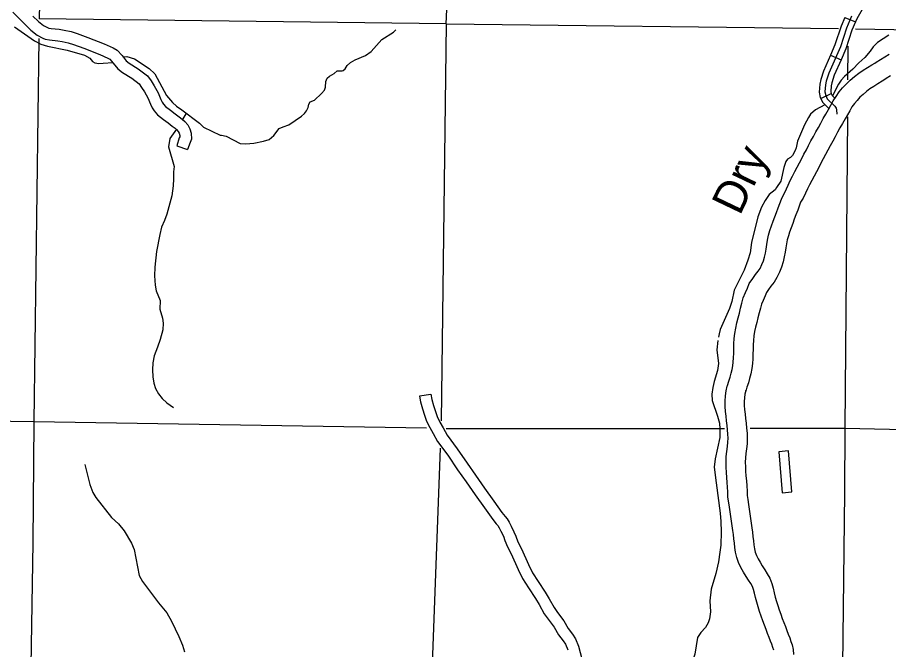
# Model space of a CAD drawing. Extents: x 0 to 3171, y 0 to 2059.
# Drawn here: x 1493 to 1682.3, y 804.5 to 941.8 of the extents above; entities that cross this region are included whole.
import ezdxf

# ---------------------------------------------------------------- set-up
doc = ezdxf.new("R2010")
doc.units = 0
for name, color, linetype in [('Level 10', 7, 'Continuous'), ('Level 32', 7, 'Continuous'), ('Level 35', 7, 'Continuous'), ('Level 46', 7, 'Continuous'), ('Level 5', 7, 'Continuous'), ('Level 57', 7, 'Continuous')]:
    doc.layers.add(name, color=color, linetype=linetype)

msp = doc.modelspace()

# ---------------------------------------------------------------- linework, layer by layer
at = {"layer": 'Level 10'}
for p, q in [((1647.22, 861.7), (1647.25, 861.83)), ((1651.23, 860.6), (1651.27, 860.73))]:
    msp.add_line(p, q, dxfattribs=at)
for points in [[(1647.25, 861.83), (1647.54, 862.76), (1647.83, 863.63), (1648.08, 864.48), (1648.32, 865.31), (1648.46, 866.06), (1648.54, 866.88), (1648.58, 867.81), (1648.63, 868.81), (1648.66, 869.8), (1648.68, 870.86), (1648.76, 872), (1648.88, 873.13), (1649.07, 874.29), (1649.32, 875.42), (1649.59, 876.5), (1649.85, 877.56), (1650.12, 878.63), (1650.4, 879.7), (1650.71, 880.86), (1651.21, 882.04), (1651.64, 882.92), (1652.01, 883.94), (1652.77, 885.04), (1653.39, 885.89), (1653.97, 886.62), (1654.34, 887.23), (1654.76, 888.12), (1655.08, 888.91), (1655.32, 889.71), (1655.51, 890.55), (1655.67, 891.45), (1655.83, 892.41), (1656, 893.41), (1656.22, 894.45), (1656.51, 895.49), (1656.84, 896.51), (1657.19, 897.48), (1657.53, 898.43), (1657.9, 899.42), (1658.28, 900.4), (1658.65, 901.34), (1658.98, 902.28), (1660.09, 904.54), (1660.49, 905.36), (1660.92, 906.31), (1661.42, 907.31), (1661.92, 908.27), (1662.41, 909.22), (1662.9, 910.17), (1663.4, 911.12), (1663.9, 912.08), (1664.41, 913.01), (1664.88, 913.94), (1665.42, 914.94), (1665.96, 915.91), (1666.49, 916.88), (1667.02, 917.85), (1667.54, 918.82), (1668.09, 919.81), (1668.65, 920.78), (1669.2, 921.76), (1669.71, 922.68), (1670.25, 923.64), (1670.87, 924.62), (1671.54, 925.57), (1672.29, 926.49), (1673.1, 927.35), (1673.96, 928.16), (1674.86, 928.92), (1675.82, 929.64), (1676.79, 930.28), (1677.73, 930.86), (1678.66, 931.44), (1679.3, 931.84), (1679.59, 932.02), (1680.53, 932.6), (1681.47, 933.18), (1682.41, 933.76)], [(1682.72, 929.06), (1681.79, 928.48), (1681.5, 928.3), (1680.86, 927.9), (1679.94, 927.33), (1679.04, 926.77), (1678.21, 926.22), (1677.45, 925.66), (1676.73, 925.05), (1676.05, 924.41), (1675.43, 923.75), (1674.86, 923.05), (1674.33, 922.31), (1673.84, 921.51), (1673.34, 920.64), (1672.83, 919.73), (1672.27, 918.72), (1671.72, 917.76), (1671.2, 916.82), (1670.68, 915.86), (1670.14, 914.88), (1669.61, 913.9), (1669.07, 912.94), (1668.58, 912.02), (1668.09, 911.06), (1667.57, 910.11), (1667.09, 909.18), (1666.6, 908.25), (1666.11, 907.31), (1665.62, 906.35), (1665.13, 905.42), (1664.68, 904.52), (1664.26, 903.58), (1663.73, 902.51), (1663.17, 901.62), (1662.55, 899.88), (1662.16, 898.89), (1661.79, 897.94), (1661.45, 897), (1661.11, 896.06), (1660.78, 895.15), (1660.5, 894.3), (1660.27, 893.47), (1660.09, 892.62), (1659.94, 891.72), (1659.78, 890.76), (1659.6, 889.73), (1659.36, 888.64), (1659.02, 887.52), (1658.57, 886.43), (1658.01, 885.25), (1657.4, 884.25), (1656.72, 883.38), (1656.17, 882.63), (1655.74, 882.01), (1655.48, 881.3), (1655, 880.31), (1654.66, 879.5), (1654.43, 878.64), (1654.16, 877.6), (1653.9, 876.54), (1653.63, 875.49), (1653.38, 874.47), (1653.17, 873.51), (1653.01, 872.57), (1652.91, 871.62), (1652.84, 870.68), (1652.83, 869.69), (1652.79, 868.64), (1652.75, 867.63), (1652.7, 866.59), (1652.59, 865.47), (1652.38, 864.34), (1652.08, 863.33), (1651.81, 862.39), (1651.51, 861.48), (1651.23, 860.6)], [(1657.34, 804.29), (1657.12, 804.9), (1656.9, 805.59), (1656.62, 806.29), (1656.3, 807.11), (1655.97, 807.96), (1655.65, 808.82), (1655.29, 809.74), (1654.94, 810.72), (1654.59, 811.69), (1654.24, 812.7), (1653.92, 813.74), (1653.63, 814.77), (1653.39, 815.79), (1653.18, 816.7), (1652.94, 817.5), (1652.69, 818.16), (1652.32, 818.81), (1651.87, 819.56), (1651.34, 820.35), (1650.76, 821.27), (1650.19, 822.27), (1649.7, 823.35), (1649.31, 824.46), (1649.05, 825.58), (1648.9, 826.6), (1648.78, 827.56), (1648.67, 828.49), (1648.55, 829.42), (1648.43, 830.35), (1648.29, 831.32), (1648.14, 832.32), (1648, 833.34), (1647.86, 834.37), (1647.72, 835.38), (1647.56, 836.36), (1647.36, 837.59), (1647.38, 838.75), (1647.31, 839.71), (1647.22, 840.76), (1647.13, 841.82), (1647.05, 842.92), (1646.99, 844.05), (1646.98, 845.2), (1647.02, 846.37), (1647.13, 847.51), (1647.26, 848.56), (1647.36, 849.47), (1647.39, 850.34), (1647.37, 851.22), (1647.28, 852.15), (1647.18, 853.15), (1647.06, 854.16), (1646.96, 855.17), (1646.85, 856.2), (1646.77, 857.27), (1646.74, 858.4), (1646.81, 859.55), (1646.97, 860.69), (1647.22, 861.7)], [(1651.27, 860.73), (1651.07, 859.9), (1650.96, 859.13), (1650.91, 858.33), (1650.93, 857.49), (1651, 856.57), (1651.1, 855.6), (1651.21, 854.61), (1651.32, 853.6), (1651.43, 852.57), (1651.53, 851.48), (1651.56, 850.33), (1651.52, 849.17), (1651.4, 848.06), (1651.27, 847.05), (1651.18, 846.1), (1651.15, 845.15), (1651.16, 844.18), (1651.2, 843.19), (1651.29, 842.16), (1651.38, 841.1), (1651.46, 840.03), (1651.55, 838.87), (1651.53, 837.9), (1651.67, 837.05), (1651.85, 835.98), (1651.99, 834.93), (1652.13, 833.92), (1652.27, 832.91), (1652.41, 831.91), (1652.55, 830.93), (1652.68, 829.96), (1652.81, 829.01), (1652.92, 828.07), (1653.03, 827.17), (1653.15, 826.35), (1653.32, 825.62), (1653.57, 824.9), (1653.91, 824.17), (1654.34, 823.41), (1654.84, 822.62), (1655.39, 821.78), (1655.92, 820.91), (1656.47, 819.93), (1656.89, 818.84), (1657.21, 817.77), (1657.44, 816.75), (1657.67, 815.81), (1657.92, 814.91), (1658.19, 814.01), (1658.52, 813.08), (1658.86, 812.12), (1659.19, 811.2), (1659.54, 810.31), (1659.87, 809.43), (1660.19, 808.61), (1660.49, 807.83), (1660.82, 807.02), (1661.07, 806.23), (1661.34, 805.47), (1661.58, 804.5), (1661.6, 803.4)]]:
    msp.add_lwpolyline(points, dxfattribs=at)
at = {"layer": 'Level 32'}
for p, q in [((1672.77, 941.76), (1675.07, 940.79)), ((1669.65, 933.56), (1671.95, 932.56)), ((1667.54, 924.17), (1669.79, 925.25))]:
    msp.add_line(p, q, dxfattribs=at)
for points in [[(1679.83, 947.9), (1678.95, 946.55), (1676.56, 943.45), (1675.35, 941.44), (1675.07, 940.79)], [(1674.23, 942.01), (1673.13, 939.41), (1671.8, 935.36), (1669.31, 929.63), (1668.75, 927.91), (1668.56, 927.11), (1668.46, 925.62), (1668.63, 924.77), (1668.96, 924.09), (1670.6, 922.52), (1670.87, 922.07), (1670.97, 921.72), (1671.02, 920.74)], [(1672.77, 941.76), (1671.96, 939.85), (1670.63, 935.8), (1669.65, 933.56)], [(1675.07, 940.79), (1674.3, 938.97), (1672.97, 934.91), (1671.95, 932.56)], [(1669.65, 933.56), (1668.14, 930.08), (1667.54, 928.25), (1667.31, 927.29), (1667.2, 925.53), (1667.44, 924.37), (1667.54, 924.17)], [(1671.95, 932.56), (1670.48, 929.19), (1669.95, 927.57), (1669.8, 926.92), (1669.72, 925.71), (1669.83, 925.18), (1669.79, 925.25)], [(1667.54, 924.17), (1667.93, 923.34), (1669.33, 922)], [(1669.79, 925.25), (1669.99, 924.84), (1670.62, 924.23)]]:
    msp.add_lwpolyline(points, dxfattribs=at)
at = {"layer": 'Level 35'}
for points in [[(1492.36, 939.7), (1496.67, 936.65), (1498.08, 935.99), (1499.48, 935.54), (1503.77, 934.63), (1507.54, 933.56), (1508.71, 932.95), (1509.28, 932.19), (1509.83, 931.89), (1510.7, 931.78), (1511.63, 931.86), (1513.73, 931.94)], [(1537.06, 916.18), (1537.35, 916.19), (1538.34, 916), (1541.37, 914.36), (1542.6, 914.31), (1544.32, 914.42), (1546.46, 914.87), (1547.69, 915.26), (1548.69, 916.09), (1549.85, 917.61), (1550.69, 918.03), (1551.99, 918.4), (1554.74, 920.29), (1555.35, 920.89), (1555.77, 921.46), (1556.14, 922.18), (1556.31, 922.94), (1556.57, 923.46), (1557.53, 923.78), (1559.06, 925.22), (1559.72, 925.96), (1559.94, 926.63), (1560.02, 927.85), (1560.31, 928.58), (1560.78, 929.02), (1561.81, 929.62), (1562.45, 930.19), (1563.52, 930.19), (1563.75, 930.26), (1564.23, 930.62), (1564.66, 931.35), (1565.35, 931.96), (1566.36, 932.54), (1568.58, 933.49), (1569.87, 934.33), (1572.16, 936.94), (1574.72, 938.55), (1575.19, 939.08)], [(1682.35, 937.88), (1679.9, 936.33), (1678.93, 935.39), (1678.3, 934.45), (1677.09, 933.04), (1675.79, 931.9), (1674.52, 930.54), (1672.69, 928.94), (1672.01, 928.12), (1671.41, 927.29), (1670.11, 924.72)], [(1515.91, 933.21), (1516.75, 933.3), (1518.45, 932.79), (1521.6, 930.64), (1522.81, 929.49), (1525.37, 924.77), (1526.68, 923.27), (1527.56, 922.5), (1528.74, 921.7), (1532.53, 918.78), (1533.4, 917.95), (1537.06, 916.18)], [(1668.42, 922.79), (1666.37, 921.7), (1665.29, 920.75), (1664.85, 920.05), (1664.02, 918.46), (1662.49, 914.87), (1662.22, 913.42), (1661.99, 912.86), (1661.43, 911.76), (1660.99, 911.33), (1660.29, 910.95), (1659.93, 910.46), (1659.52, 909.15), (1658.84, 906.23), (1657.92, 904.79), (1657.63, 904.31), (1656.34, 903.29), (1655.43, 901.99), (1654.66, 900.52), (1653.84, 898.42), (1652.52, 892.88), (1652.19, 890.65), (1651.66, 889.01), (1650.88, 886.86), (1648.75, 882.49), (1648.23, 880.05), (1647.73, 878.56), (1645.68, 874.01), (1645.43, 873.04), (1645.34, 872.3)], [(1529.67, 920.98), (1528.84, 919.62)], [(1527.51, 917.47), (1526.13, 915.45), (1525.84, 913.62), (1527.05, 909.38), (1526.88, 908.23), (1526.92, 906.71), (1526.8, 905.16), (1526.51, 903), (1525.41, 899.04), (1524.95, 897.62), (1524.27, 896.17), (1523.9, 894.61), (1523.17, 890.91), (1522.84, 887.53), (1522.77, 885.66), (1522.9, 883.59), (1523.1, 882.41), (1523.99, 880.31), (1523.9, 878.37), (1524.53, 876.46), (1524.65, 875.36), (1524.57, 873.92), (1523.99, 871.81), (1523.39, 870.13)], [(1645.16, 871.58), (1644.97, 869.54), (1645.3, 866.61), (1645.11, 865.06), (1644.37, 862.7), (1644.09, 861.4), (1643.9, 859.91), (1643.94, 858.55), (1645.1, 855.16), (1645.51, 853.66), (1645.64, 852.41), (1645.58, 850.5), (1644.62, 845.9), (1644.37, 844.05), (1644.8, 840.67), (1645.71, 834.11), (1645.86, 832.25), (1645.92, 830.03), (1645.84, 827.16), (1645.59, 825.58), (1645.35, 823.54)], [(1523.39, 870.13), (1522.66, 868.23), (1522.39, 866.75), (1522.3, 865.21), (1522.43, 863.68), (1522.65, 862.31), (1523.01, 861.18), (1523.63, 859.97), (1524.45, 858.98), (1525.42, 858.07), (1526.86, 857.06)], [(1507.61, 844.65), (1508.69, 840.31), (1509.38, 838.55), (1510.05, 837.47), (1513.42, 833.11), (1514.94, 831.75), (1516.15, 830.21), (1517.74, 827.54), (1518.33, 826.22), (1519.4, 820.53), (1520.17, 819.27), (1523.64, 814.63), (1525.43, 812.42), (1526.44, 810.6), (1528.04, 807.31), (1528.84, 805.38), (1529.28, 803.93)], [(1645.35, 823.54), (1644.72, 820.99), (1643.75, 817.59), (1643.46, 815.03), (1643.55, 812.67), (1643.35, 811.1), (1643.09, 810.23), (1642.49, 809.26), (1641.47, 808.16), (1640.78, 807.11), (1640.21, 803.42), (1639.58, 801.74), (1638.55, 800.25), (1637.38, 798.82), (1636.78, 797.75), (1636.63, 796.78), (1636.51, 793.55), (1635.17, 789.82), (1635.03, 788.85)]]:
    msp.add_lwpolyline(points, dxfattribs=at)
at = {"layer": 'Level 46'}
for points in [[(1491.97, 942.93), (1494.57, 940.29), (1495.91, 939.02), (1497.26, 937.89), (1498.5, 937.29), (1499.03, 937.06), (1499.93, 936.87), (1501.76, 936.7), (1502.71, 936.56), (1503.98, 936.27), (1505.14, 935.9), (1507.39, 935.08), (1510.9, 933.69), (1512.65, 932.92), (1513.03, 932.69), (1513.81, 931.83), (1514.83, 930.57), (1515.79, 929.78), (1517.81, 928.57), (1519.4, 927.31), (1519.96, 926.55), (1520.57, 925.6), (1521.32, 924.3), (1521.88, 922.92), (1522.29, 922.12), (1522.72, 921.45), (1523.45, 920.6), (1524.74, 919.61), (1525.73, 918.85), (1526.6, 918.16), (1527.23, 917.7), (1527.58, 917.41), (1527.91, 917.02), (1528.12, 916.62), (1528.28, 916.14), (1528.3, 915.85), (1528.16, 915.58), (1527.59, 913.84), (1529.97, 913.06)], [(1496.32, 942.07), (1497.57, 940.89), (1498.63, 940.01), (1499.54, 939.57), (1499.8, 939.45), (1500.31, 939.35), (1502.06, 939.18), (1503.17, 939.02), (1504.65, 938.68), (1505.94, 938.26), (1508.28, 937.41), (1511.86, 936), (1513.8, 935.15), (1514.64, 934.64), (1515.71, 933.46), (1516.62, 932.34), (1517.24, 931.83), (1519.23, 930.63), (1521.21, 929.07), (1522.03, 927.96), (1522.71, 926.89), (1523.57, 925.4), (1524.15, 923.96), (1524.46, 923.36), (1524.73, 922.95), (1525.17, 922.43), (1526.26, 921.59), (1527.27, 920.82), (1528.11, 920.15), (1528.78, 919.67), (1529.35, 919.18), (1529.99, 918.44), (1530.43, 917.6), (1530.75, 916.62), (1530.83, 915.33), (1530.48, 914.62), (1529.97, 913.06)], [(1582.84, 859.89), (1580.37, 859.48), (1580.6, 858.26), (1580.97, 856.77), (1581.43, 855.34), (1581.9, 854.07), (1582.56, 852.7), (1583.29, 851.38), (1584.29, 849.68), (1586.47, 846.66), (1588.63, 843.49), (1590.48, 840.88), (1592.46, 838.05), (1594.44, 835.27), (1596.27, 832.72), (1597.04, 831.77), (1597.34, 831.4), (1597.63, 830.93), (1598.05, 830.14), (1598.59, 829.06), (1598.92, 828.18), (1599.48, 826.79), (1600.28, 825.27), (1601.77, 821.86), (1602.72, 819.89), (1604.04, 817.83), (1605.57, 815.57), (1606.33, 814.25), (1607.47, 812.2), (1608.33, 811.04)], [(1582.83, 859.94), (1583.04, 858.79), (1583.37, 857.46), (1583.79, 856.16), (1584.2, 855.05), (1584.78, 853.85), (1585.46, 852.62), (1586.39, 851.06), (1588.52, 848.09), (1590.68, 844.91), (1592.53, 842.32), (1594.5, 839.49), (1596.48, 836.72), (1598.26, 834.24), (1598.99, 833.34), (1599.39, 832.84), (1599.81, 832.16), (1600.27, 831.28), (1600.88, 830.06), (1601.25, 829.09), (1601.75, 827.84), (1602.53, 826.36), (1604.04, 822.9), (1604.9, 821.12), (1606.13, 819.21), (1607.69, 816.89), (1608.51, 815.48), (1609.58, 813.56), (1610.34, 812.52)], [(1610.33, 812.53), (1611.68, 810.67), (1612.64, 809.06), (1613.63, 807.77), (1614.26, 806.77), (1614.93, 805.17), (1615.62, 802.45)], [(1608.31, 811.06), (1609.58, 809.29), (1610.56, 807.66), (1611.57, 806.33), (1612.04, 805.6), (1612.55, 804.37)]]:
    msp.add_lwpolyline(points, dxfattribs=at)
at = {"layer": 'Level 5'}
for points in [[(1498.56, 980.12), (1497.71, 941.45)], [(1586.14, 940.38), (1586.39, 945.07), (1586.87, 979.5)], [(1586.14, 940.38), (1497.71, 941.45)], [(1586.14, 940.38), (1585.04, 854.15)], [(1586.14, 940.38), (1671.39, 939.37)], [(1675.08, 939.32), (1687.61, 939.08)], [(1497.65, 937.2), (1496.54, 853.94)], [(1673.44, 935.51), (1673.38, 928.22)], [(1673.32, 920.19), (1672.77, 852.52)], [(1496.54, 853.94), (1436.67, 854.81)], [(1496.54, 853.94), (1496.32, 827.64), (1495.33, 765.28)], [(1581.86, 852.52), (1496.54, 853.94)], [(1586.14, 852.47), (1646.59, 852.5)], [(1652.19, 852.51), (1672.77, 852.52)], [(1672.77, 852.52), (1672.72, 838.55), (1671.92, 769.6)], [(1672.77, 852.52), (1756.71, 850.63)], [(1584.85, 848.18), (1581.7, 764.3)]]:
    msp.add_lwpolyline(points, dxfattribs=at)
at = {"layer": 'Level 57'}
for p, q in [((1660.51, 847.6), (1658.44, 847.43)), ((1658.44, 847.43), (1659.19, 838.5)), ((1661.26, 838.68), (1660.51, 847.6)), ((1659.19, 838.5), (1661.26, 838.68))]:
    msp.add_line(p, q, dxfattribs=at)

# ---------------------------------------------------------------- texts
at = {"layer": 'Level 35'}
msp.add_text('Dry', height=7.04, rotation=64.4541, dxfattribs=at).set_placement((1649.95, 898.52))

doc.saveas('drawing.dxf')
